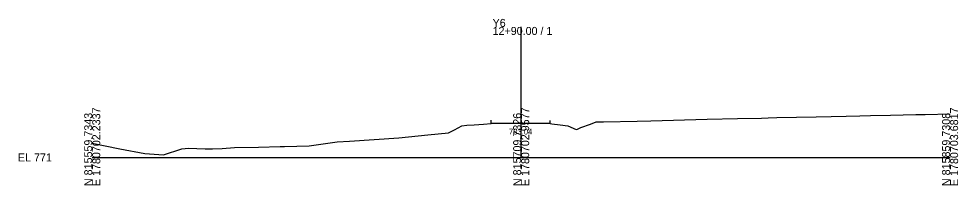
# Model space of a CAD drawing. Extents: x -26 to 1603, y -10 to 6024.
# Drawn here: x -25.7 to 302.8, y 3990.3 to 4048.5 of the extents above; entities that cross this region are included whole.
import ezdxf

# ---------------------------------------------------------------- set-up
doc = ezdxf.new("R2010")
doc.units = 0
for name, color, linetype in [('Exist Cross Section Cell', 7, 'Continuous'), ('Exist XS Center Line Elevation Label', 7, 'Continuous'), ('Exist XS Ground Line', 7, 'Continuous'), ('Prop XS EOT Tick Mark', 7, 'Continuous'), ('Prop XS Finish Grade Pavement', 7, 'Continuous')]:
    doc.layers.add(name, color=color, linetype=linetype)

msp = doc.modelspace()

# ---------------------------------------------------------------- linework, layer by layer
at = {"layer": 'Exist Cross Section Cell'}
for p, q in [((150, 4000), (150, 4045.64)), ((0, 4000), (150, 4000)), ((150, 4000), (300, 4000))]:
    msp.add_line(p, q, dxfattribs=at)
at = {"layer": 'Exist XS Ground Line'}
for p, q in [((272.12, 4014.64), (279.15, 4014.79)), ((279.15, 4014.79), (287.99, 4014.98)), ((287.99, 4014.98), (291.27, 4015.06)), ((291.27, 4015.06), (300, 4015.21)), ((133.59, 4011.37), (136.82, 4011.64)), ((136.82, 4011.64), (139.45, 4011.86)), ((139.45, 4011.86), (148.85, 4012.03)), ((148.85, 4012.03), (149.65, 4012.05)), ((149.65, 4012.05), (150, 4012.04)), ((150, 4012.04), (150.55, 4012.03)), ((150.55, 4012.03), (160.1, 4011.84)), ((160.1, 4011.84), (160.68, 4011.8)), ((160.68, 4011.8), (163.67, 4011.41)), ((163.67, 4011.41), (166.34, 4011.02)), ((170.81, 4010.46), (174.19, 4011.65)), ((174.19, 4011.65), (176.23, 4012.45)), ((176.23, 4012.45), (178.76, 4012.47)), ((178.76, 4012.47), (190.6, 4012.68)), ((190.6, 4012.68), (195.37, 4012.76)), ((195.37, 4012.76), (215, 4013.38)), ((215, 4013.38), (225.7, 4013.59)), ((225.7, 4013.59), (233.99, 4013.8)), ((233.99, 4013.8), (236.37, 4013.87)), ((236.37, 4013.87), (239.41, 4013.93)), ((239.41, 4013.93), (253.14, 4014.22)), ((253.14, 4014.22), (263.7, 4014.46)), ((263.7, 4014.46), (268.4, 4014.56)), ((268.4, 4014.56), (272.12, 4014.64)), ((117.36, 4007.94), (124.58, 4008.6)), ((124.58, 4008.6), (126.63, 4009.61)), ((126.63, 4009.61), (129.27, 4011.05)), ((129.27, 4011.05), (131.01, 4011.25)), ((131.01, 4011.25), (133.59, 4011.37)), ((166.34, 4011.02), (169.27, 4009.74)), ((169.27, 4009.74), (169.65, 4009.94)), ((169.65, 4009.94), (170.81, 4010.46)), ((0, 4005.06), (9.62, 4003.07)), ((75.88, 4004.05), (85.65, 4005.5)), ((85.65, 4005.5), (89.92, 4005.67)), ((89.92, 4005.67), (107.26, 4006.82)), ((107.26, 4006.82), (117.36, 4007.94)), ((9.62, 4003.07), (18.35, 4001.43)), ((24.92, 4000.87), (31.33, 4003.03)), ((31.33, 4003.03), (33.69, 4003.3)), ((33.69, 4003.3), (39.5, 4003.04)), ((39.5, 4003.04), (42.08, 4003)), ((42.08, 4003), (45.45, 4003.15)), ((45.45, 4003.15), (49.72, 4003.45)), ((49.72, 4003.45), (58.17, 4003.64)), ((58.17, 4003.64), (65.66, 4003.85)), ((65.66, 4003.85), (67.27, 4003.79)), ((67.27, 4003.79), (75.88, 4004.05)), ((18.35, 4001.43), (24.92, 4000.87))]:
    msp.add_line(p, q, dxfattribs=at)
at = {"layer": 'Prop XS EOT Tick Mark'}
for p, q in [((139.45, 4011.99), (139.45, 4012.99)), ((160.11, 4011.96), (160.11, 4012.96))]:
    msp.add_line(p, q, dxfattribs=at)
at = {"layer": 'Prop XS Finish Grade Pavement'}
for p, q in [((139.45, 4011.99), (148.85, 4012.15)), ((148.85, 4012.15), (149.65, 4012.17)), ((149.65, 4012.17), (150, 4012.17)), ((150, 4012.17), (150.55, 4012.16)), ((150.55, 4012.16), (160.11, 4011.96))]:
    msp.add_line(p, q, dxfattribs=at)

# ---------------------------------------------------------------- texts
at = {"layer": 'Exist Cross Section Cell'}
for s, p in [('Y6', (140, 4045.64)), ('12+90.00 / 1', (140, 4042.84)), ('EL 771', (-26, 3998.6))]:
    msp.add_text(s, height=2.8, dxfattribs=at).set_placement(p)
for s, p in [('N 815559.7343', (0, 3990)), ('E 1780702.2337', (2.8, 3990)), ('N 815709.7326', (150, 3990)), ('E 1780702.9577', (152.8, 3990)), ('N 815859.7308', (300, 3990)), ('E 1780703.6817', (302.8, 3990))]:
    msp.add_text(s, height=2.8, rotation=90, dxfattribs=at).set_placement(p)
at = {"layer": 'Exist XS Center Line Elevation Label'}
msp.add_text('783.04', height=2, dxfattribs=at).set_placement((145.72, 4008.04))

doc.saveas('drawing.dxf')
